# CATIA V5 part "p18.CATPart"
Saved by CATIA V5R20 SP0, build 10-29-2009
Part number: p18
Bounding box of the stored display mesh (mm): x -31.857 to -18.143, y -76.692 to -23.308, z -26.692 to 26.692
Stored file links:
  D:\Dropbox\IAO_2011\MMS_GR2\IAO_2011_1439_jlicbarski\p18.CATPart
  D:\Dropbox\IAO_2011\MMS_GR2\IAO_2011_1439_jlicbarski\train.CATProduct
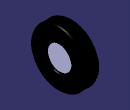
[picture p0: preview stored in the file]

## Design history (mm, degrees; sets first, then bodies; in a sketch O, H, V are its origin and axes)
AxisSystem1: origin (0, 0, 0), X (1, 0, 0), Y (0, 1, 0), Z (0, 0, 1)
Set1
  Plane1: linked copy from another document
  Line1: linked copy from another document
  Plane2: linked copy from another document
Body1 (main body)
  Sketch1 on Plane1, origin (-20, 0, 0), H (0, 1, 0), V (0, 0, 1)
    circle A1 centre (-50, 0) radius 11.5
    reference projected point E1 (-50, 0) from Line1
    radius A1 = 11.5
    distance A1 E1 = 11.5
  Pad1: profile Sketch1, direction (-1, 0, 0), length 10
  Sketch2 on Plane2, origin (0, -50, 0), H (-1, 0, 0), V (0, 0.9048, 0.4258)
    line L1 (20.7294, 26.6967) -> (29.543, 26.6967)
    line L2 (31.857, 24.3827) -> (31.857, 13.9753)
    line L3 (29.3817, 11.5) -> (20.5765, 11.5)
    line L4 (18.1427, 13.9338) -> (18.1427, 24.11)
    reference projected line E1 (40, 0) -> (0, 0) from Line1
    reference projected line E2 (20, -11.5) -> (20, 11.5) from edge [face of Pad1 from Sketch1.A1 | start face of Pad1]
    reference projected line E3 (30, -11.5) -> (30, 11.5) from edge [end face of Pad1 | face of Pad1 from Sketch1.A1]
    arc A1 centre (29.543, 24.3827) radius 2.314 from (29.543, 26.6967) to (31.857, 24.3827) cw
    arc A2 centre (20.7294, 24.11) radius 2.5867 from (20.7294, 26.6967) to (18.1427, 24.11) ccw
    arc A3 centre (29.3817, 13.9753) radius 2.4753 from (31.857, 13.9753) to (29.3817, 11.5) cw
    arc A4 centre (20.5765, 13.9338) radius 2.4338 from (18.1427, 13.9338) to (20.5765, 11.5) ccw
    distance L3 E1 = 11.5
    distance L4 E2 = 1.8573
    distance L2 E3 = 1.857
    distance L1 L3 = 15.1967
  Shaft1: profile Sketch2, axis Line1, angle 360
